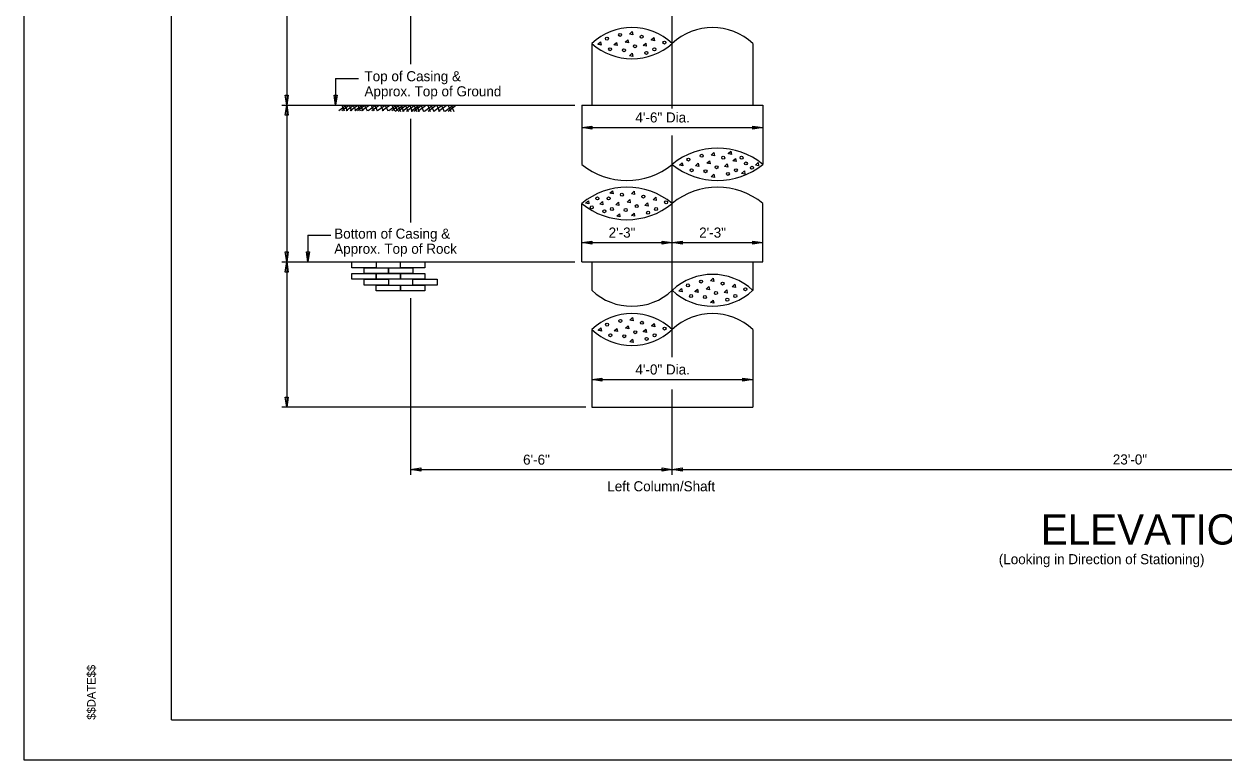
# Model space of a CAD drawing. Extents: x -437.9 to -365.7, y 404.2 to 448.2.
# Drawn here: x -437.93 to -408.12, y 404.21 to 422.49 of the extents above; entities that cross this region are included whole.
import ezdxf

# ---------------------------------------------------------------- set-up
doc = ezdxf.new("R2010")
doc.units = 0
for name, color, linetype in [('BR_AUTO DIMENSION', 7, 'Continuous'), ('BR_BORDER LINES', 7, 'Continuous'), ('BR_CENTER LINES', 7, 'Continuous'), ('BR_CONCRETE', 7, 'Continuous'), ('BR_GROUND LINES', 7, 'Continuous'), ('BR_REBAR', 7, 'Continuous'), ('BR_TEXT', 7, 'Continuous'), ('RD_SHT_IplotShp', 7, 'Continuous')]:
    doc.layers.add(name, color=color, linetype=linetype)

msp = doc.modelspace()

# ---------------------------------------------------------------- linework, layer by layer
at = {"layer": 'BR_AUTO DIMENSION'}
for p, q in [((-431.404, 430.977), (-431.404, 412.977)), ((-428.327, 426.352), (-428.327, 421.492)), ((-430.192, 421.141), (-430.192, 420.474)), ((-430.192, 421.141), (-429.622, 421.141)), ((-430.112, 420.34), (-429.926, 420.474)), ((-430.039, 420.34), (-429.853, 420.474)), ((-430.036, 420.474), (-429.975, 420.331)), ((-429.963, 420.474), (-429.902, 420.331)), ((-429.93, 420.34), (-429.744, 420.474)), ((-429.853, 420.474), (-429.792, 420.331)), ((-429.826, 420.34), (-429.64, 420.474)), ((-429.75, 420.474), (-429.689, 420.331)), ((-429.716, 420.34), (-429.53, 420.474)), ((-429.649, 420.34), (-429.463, 420.474)), ((-429.64, 420.474), (-429.579, 420.331)), ((-429.573, 420.474), (-429.512, 420.331)), ((-429.545, 420.34), (-429.359, 420.474)), ((-429.469, 420.474), (-429.408, 420.331)), ((-429.381, 420.34), (-429.195, 420.474)), ((-429.304, 420.474), (-429.243, 420.331)), ((-429.292, 420.34), (-429.106, 420.474)), ((-429.216, 420.474), (-429.155, 420.331)), ((-429.149, 420.34), (-428.963, 420.474)), ((-429.073, 420.474), (-429.012, 420.331)), ((-429.033, 420.34), (-428.847, 420.474)), ((-428.957, 420.474), (-428.896, 420.331)), ((-428.868, 420.34), (-428.682, 420.474)), ((-428.795, 420.34), (-428.609, 420.474)), ((-428.792, 420.474), (-428.731, 420.331)), ((-428.719, 420.474), (-428.658, 420.331)), ((-428.711, 420.33), (-428.525, 420.465)), ((-428.638, 420.33), (-428.452, 420.465)), ((-428.635, 420.465), (-428.574, 420.321)), ((-428.562, 420.465), (-428.501, 420.321)), ((-428.529, 420.33), (-428.343, 420.465)), ((-428.452, 420.465), (-428.391, 420.321)), ((-428.425, 420.33), (-428.239, 420.465)), ((-428.349, 420.465), (-428.288, 420.321)), ((-428.315, 420.33), (-428.129, 420.465)), ((-428.248, 420.33), (-428.062, 420.465)), ((-428.239, 420.465), (-428.178, 420.321)), ((-428.172, 420.465), (-428.111, 420.321)), ((-428.144, 420.33), (-427.958, 420.465)), ((-428.068, 420.465), (-428.007, 420.321)), ((-427.98, 420.33), (-427.794, 420.465)), ((-427.903, 420.465), (-427.842, 420.321)), ((-427.891, 420.33), (-427.705, 420.465)), ((-427.815, 420.465), (-427.754, 420.321)), ((-427.748, 420.33), (-427.562, 420.465)), ((-427.672, 420.465), (-427.611, 420.321)), ((-427.632, 420.33), (-427.446, 420.465)), ((-427.556, 420.465), (-427.495, 420.321)), ((-427.467, 420.33), (-427.281, 420.465)), ((-427.394, 420.33), (-427.208, 420.465)), ((-427.391, 420.465), (-427.33, 420.321)), ((-427.318, 420.465), (-427.257, 420.321)), ((-428.327, 420.137), (-428.327, 417.562)), ((-424.077, 419.921), (-419.577, 419.921)), ((-430.878, 417.249), (-430.878, 416.582)), ((-430.878, 417.249), (-430.308, 417.249)), ((-424.077, 417.062), (-421.827, 417.062)), ((-421.827, 417.062), (-419.577, 417.062)), ((-428.327, 415.68), (-428.327, 411.294)), ((-423.827, 413.662), (-419.827, 413.662)), ((-423.973, 412.977), (-431.528, 412.977)), ((-428.327, 411.427), (-398.827, 411.427)), ((-421.827, 411.634), (-421.827, 411.634))]:
    msp.add_line(p, q, dxfattribs=at)
for points in [[(-431.367, 420.724), (-431.404, 420.474), (-431.442, 420.724)], [(-430.154, 420.724), (-430.192, 420.474), (-430.229, 420.724)], [(-431.442, 420.224), (-431.404, 420.474), (-431.367, 420.224)], [(-423.827, 419.883), (-424.077, 419.921), (-423.827, 419.958)], [(-419.827, 419.958), (-419.577, 419.921), (-419.827, 419.883)], [(-423.827, 417.024), (-424.077, 417.062), (-423.827, 417.099)], [(-422.077, 417.099), (-421.827, 417.062), (-422.077, 417.024)], [(-421.577, 417.024), (-421.827, 417.062), (-421.577, 417.099)], [(-419.827, 417.099), (-419.577, 417.062), (-419.827, 417.024)], [(-431.367, 416.832), (-431.404, 416.582), (-431.442, 416.832)], [(-430.841, 416.832), (-430.878, 416.582), (-430.916, 416.832)], [(-431.442, 416.332), (-431.404, 416.582), (-431.367, 416.332)], [(-423.577, 413.625), (-423.827, 413.662), (-423.577, 413.7)], [(-420.077, 413.7), (-419.827, 413.662), (-420.077, 413.625)], [(-431.367, 413.227), (-431.404, 412.977), (-431.442, 413.227)], [(-428.077, 411.39), (-428.327, 411.427), (-428.077, 411.465)], [(-422.077, 411.465), (-421.827, 411.427), (-422.077, 411.39)], [(-421.577, 411.39), (-421.827, 411.427), (-421.577, 411.465)]]:
    msp.add_lwpolyline(points, close=True, dxfattribs=at)
at = {"layer": 'BR_BORDER LINES'}
for q in [(-434.265, 447.213), (-366.931, 405.213)]:
    msp.add_line((-434.265, 405.213), q, dxfattribs=at)
at = {"layer": 'BR_CENTER LINES'}
for p, q in [((-421.827, 420.393), (-421.827, 424.816)), ((-421.827, 414.221), (-421.827, 419.722)), ((-421.827, 411.294), (-421.827, 413.411))]:
    msp.add_line(p, q, dxfattribs=at)
at = {"layer": 'BR_CONCRETE'}
for p, q in [((-423.827, 422.006), (-423.827, 420.474)), ((-419.827, 422.006), (-419.827, 420.474)), ((-424.077, 420.474), (-419.577, 420.474)), ((-424.077, 420.474), (-424.077, 419.006)), ((-419.577, 420.474), (-419.577, 419.006)), ((-424.077, 416.582), (-424.077, 418.034)), ((-419.577, 416.582), (-419.577, 418.034)), ((-424.077, 416.582), (-419.577, 416.582)), ((-423.827, 416.582), (-423.827, 415.877)), ((-419.827, 416.582), (-419.827, 415.877)), ((-423.827, 414.906), (-423.827, 412.977)), ((-419.827, 414.906), (-419.827, 412.977)), ((-423.827, 412.977), (-419.827, 412.977))]:
    msp.add_line(p, q, dxfattribs=at)
for centre, radius, start, end in [((-422.827, 420.94), 1.461, 46.811, 133.189), ((-420.827, 420.94), 1.461, 46.811, 133.189), ((-422.827, 423.14), 1.512, 228.6075, 311.3925), ((-420.702, 417.633), 1.775, 50.6575, 129.3425), ((-422.952, 420.378), 1.775, 230.6575, 309.3425), ((-420.702, 420.378), 1.775, 230.6575, 309.3425), ((-422.952, 416.662), 1.775, 50.6575, 129.3425), ((-420.702, 416.662), 1.775, 50.6575, 129.3425), ((-422.952, 419.407), 1.775, 230.6575, 309.3425), ((-420.827, 414.812), 1.461, 46.811, 133.189), ((-422.827, 416.943), 1.461, 226.811, 313.189), ((-420.827, 416.943), 1.461, 226.811, 313.189), ((-422.827, 413.841), 1.461, 46.811, 133.189), ((-420.827, 413.841), 1.461, 46.811, 133.189), ((-422.827, 415.971), 1.461, 226.811, 313.189)]:
    msp.add_arc(centre, radius, start, end, dxfattribs=at)
at = {"layer": 'BR_GROUND LINES'}
for p, q in [((-431.528, 420.474), (-424.244, 420.474)), ((-431.528, 416.582), (-424.244, 416.582))]:
    msp.add_line(p, q, dxfattribs=at)
for points in [[(-429.785, 416.582), (-429.18, 416.582), (-429.18, 416.439), (-429.785, 416.439)], [(-428.576, 416.582), (-427.971, 416.582), (-427.971, 416.439), (-428.576, 416.439)], [(-429.785, 416.296), (-429.18, 416.296), (-429.18, 416.152), (-429.785, 416.152)], [(-429.483, 416.439), (-428.878, 416.439), (-428.878, 416.296), (-429.483, 416.296)], [(-429.18, 416.296), (-428.576, 416.296), (-428.576, 416.152), (-429.18, 416.152)], [(-428.878, 416.439), (-428.273, 416.439), (-428.273, 416.296), (-428.878, 416.296)], [(-428.576, 416.296), (-427.971, 416.296), (-427.971, 416.152), (-428.576, 416.152)], [(-429.483, 416.152), (-428.878, 416.152), (-428.878, 416.009), (-429.483, 416.009)], [(-429.18, 416.009), (-428.576, 416.009), (-428.576, 415.866), (-429.18, 415.866)], [(-428.576, 416.009), (-427.971, 416.009), (-427.971, 415.866), (-428.576, 415.866)], [(-428.273, 416.152), (-427.669, 416.152), (-427.669, 416.009), (-428.273, 416.009)]]:
    msp.add_lwpolyline(points, close=True, dxfattribs=at)
at = {"layer": 'BR_REBAR'}
for points in [[(-422.819, 422.304), (-422.805, 422.223), (-422.886, 422.242)], [(-422.281, 422.157), (-422.267, 422.076), (-422.347, 422.095)], [(-423.606, 422.05), (-423.592, 421.97), (-423.672, 421.988)], [(-423.209, 422.035), (-423.195, 421.955), (-423.275, 421.973)], [(-422.927, 422.1), (-422.913, 422.02), (-422.994, 422.038)], [(-422.485, 422.018), (-422.471, 421.937), (-422.552, 421.955)], [(-422.819, 421.765), (-422.805, 421.684), (-422.886, 421.702)], [(-420.793, 419.301), (-420.779, 419.22), (-420.86, 419.238)], [(-420.372, 419.335), (-420.358, 419.254), (-420.438, 419.272)], [(-420.255, 419.154), (-420.241, 419.073), (-420.322, 419.091)], [(-421.58, 419.047), (-421.566, 418.966), (-421.647, 418.984)], [(-421.183, 419.032), (-421.169, 418.951), (-421.25, 418.97)], [(-420.902, 419.097), (-420.888, 419.016), (-420.968, 419.034)], [(-420.46, 419.015), (-420.446, 418.934), (-420.526, 418.952)], [(-419.695, 419.051), (-419.681, 418.97), (-419.761, 418.988)], [(-420.793, 418.762), (-420.779, 418.681), (-420.86, 418.699)], [(-420.036, 418.844), (-420.022, 418.763), (-420.103, 418.781)], [(-423.308, 418.351), (-423.293, 418.27), (-423.374, 418.288)], [(-422.776, 418.336), (-422.762, 418.255), (-422.842, 418.273)], [(-423.911, 418.103), (-423.897, 418.023), (-423.978, 418.041)], [(-423.562, 418.082), (-423.548, 418.001), (-423.629, 418.019)], [(-423.165, 418.067), (-423.151, 417.986), (-423.232, 418.004)], [(-422.884, 418.132), (-422.87, 418.051), (-422.95, 418.069)], [(-422.442, 418.049), (-422.428, 417.969), (-422.509, 417.987)], [(-422.237, 418.189), (-422.223, 418.108), (-422.304, 418.126)], [(-423.14, 417.78), (-423.126, 417.699), (-423.206, 417.717)], [(-422.776, 417.796), (-422.762, 417.716), (-422.842, 417.734)], [(-420.808, 416.176), (-420.794, 416.095), (-420.874, 416.113)], [(-421.594, 415.922), (-421.58, 415.841), (-421.661, 415.86)], [(-421.197, 415.907), (-421.183, 415.826), (-421.264, 415.845)], [(-420.916, 415.972), (-420.902, 415.891), (-420.983, 415.91)], [(-420.474, 415.89), (-420.46, 415.809), (-420.541, 415.827)], [(-420.269, 416.029), (-420.255, 415.948), (-420.336, 415.966)], [(-420.808, 415.637), (-420.794, 415.556), (-420.874, 415.574)], [(-422.922, 414.998), (-422.908, 414.917), (-422.988, 414.935)], [(-422.813, 415.201), (-422.799, 415.121), (-422.88, 415.139)], [(-422.275, 415.054), (-422.261, 414.974), (-422.342, 414.992)], [(-423.6, 414.948), (-423.586, 414.867), (-423.667, 414.885)], [(-423.203, 414.933), (-423.189, 414.852), (-423.27, 414.87)], [(-422.48, 414.915), (-422.466, 414.834), (-422.546, 414.853)], [(-422.813, 414.662), (-422.799, 414.581), (-422.88, 414.6)]]:
    msp.add_lwpolyline(points, close=True, dxfattribs=at)
for centre in [(-423.45, 422.128), (-423.121, 422.222), (-422.588, 422.174), (-423.37, 421.865), (-423.027, 421.84), (-422.753, 421.939), (-422.272, 421.864), (-422.022, 422.032), (-422.47, 421.774), (-421.424, 419.125), (-421.096, 419.219), (-420.562, 419.171), (-420.105, 419.171), (-421.345, 418.861), (-421.001, 418.836), (-420.727, 418.935), (-420.246, 418.861), (-419.997, 419.029), (-419.846, 418.921), (-420.444, 418.77), (-423.078, 418.253), (-423.826, 417.937), (-423.688, 418.16), (-423.407, 418.159), (-422.709, 417.97), (-422.545, 418.206), (-421.979, 418.064), (-423.514, 417.843), (-423.327, 417.896), (-422.983, 417.871), (-422.427, 417.805), (-422.229, 417.896), (-421.439, 416), (-421.11, 416.094), (-420.577, 416.046), (-420.011, 415.904), (-421.359, 415.736), (-421.015, 415.711), (-420.741, 415.81), (-420.459, 415.645), (-420.261, 415.736), (-423.444, 415.025), (-423.116, 415.119), (-422.582, 415.072), (-423.365, 414.762), (-423.021, 414.737), (-422.747, 414.836), (-422.464, 414.671), (-422.266, 414.761), (-422.017, 414.929)]:
    msp.add_circle(centre, 0.0373, dxfattribs=at)
at = {"layer": 'RD_SHT_IplotShp'}
for p, q in [((-437.931, 404.213), (-437.931, 448.213)), ((-365.931, 404.213), (-437.931, 404.213))]:
    msp.add_line(p, q, dxfattribs=at)

# ---------------------------------------------------------------- texts
at = {"layer": 'BR_TEXT'}
for s, height, p in [('Top of Casing &', 0.25, (-429.473, 421.07)), ('Approx. Top of Ground', 0.25, (-429.473, 420.695)), ('4\'-6" Dia.', 0.25, (-422.742, 420.046)), ('Bottom of Casing &', 0.25, (-430.224, 417.16)), ('2\'-3"', 0.25, (-423.408, 417.187)), ('2\'-3"', 0.25, (-421.158, 417.187)), ('Approx. Top of Rock ', 0.25, (-430.224, 416.785)), ('4\'-0" Dia.', 0.25, (-422.742, 413.787)), ('6\'-6"', 0.25, (-425.533, 411.547)), ('23\'-0"', 0.25, (-410.882, 411.552)), ('Left Column/Shaft', 0.25, (-423.44, 410.886)), ('ELEVATION', 0.75, (-412.671, 409.564)), ('(Looking in Direction of Stationing)', 0.25, (-413.715, 409.076))]:
    msp.add_text(s, height=height, dxfattribs=at).set_placement(p)
msp.add_text('$$DATE$$', height=0.2083, rotation=90, dxfattribs=at).set_placement((-436.155, 405.213))

doc.saveas('drawing.dxf')
